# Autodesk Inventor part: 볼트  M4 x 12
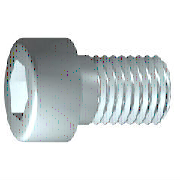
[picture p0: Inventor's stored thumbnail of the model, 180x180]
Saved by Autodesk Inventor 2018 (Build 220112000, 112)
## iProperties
IsCustomPart: 1
Created: 2012-02
Part Number: 볼트  M4 x 12
Material: 강철, 연강
Description: 6각 소켓 머리 캡 나사
Document SubType Name: Modeling
Standard: ISO 4762
Designer: mdu-01
Standard Revision: Fourth edition 2004-03-01
Standards Organization: ISO
Language: ko-KR
Size Designation: M4 x 12
Categories: <MemberInstance><Categories><Category DisplayName="조임쇠" InternalName="e4da775c-781d-43d5-af7c-5136215cf5a6" Mnemonic="FSTN"><Category DisplayName="볼트" InternalN
Density: 7.75 g/cm^3
Appearance: 강철
Author: mdu-01
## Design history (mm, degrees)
sketch "스케치1"
  geometry: L1 (-1, 0)-(12, 0); L2 (12, 0)-(12, 2); L3 (12, 2)-(1.75, 2); L4 (1.75, 2)-(1.32, 2); L5 (1.32, 2)-(0, 2); L6 (0, 2)-(0, 3.5); L7 (0, 3.5)-(-4, 3.5); L8 (-4, 3.5)-(-4, 1.732); L9 (-4, 1.732)-(-2, 1.732); L10 (-2, 1.732)-(-1, 0); L11 (-7.2, 0)-(15.2, 0) reference; L12 (0, -0.7)-(0, 4.2) reference; L13 (1.75, 2)-(0, 2)
  constraints: 22 end point, 6 parallel, 2 collinear, 2 perpendicular, 1 horizontal, 1 point on line
  dimensions: "d1" = 10.25 distance from line of L3.end L2 (= GEL); "d2" = 0.42952 distance of L4.end L3.end (computed from GAL); "d3" = 4 distance between parallel lines of L8 L6 (= KOH); "d4" = 2 distance of L8.end L9.end (= INTI); "d5" = 60 deg angle of L10 L1; "d6" = 4 diameter of L3 L1 (= GD); "d7" = 4 diameter of L5 L1 (= BDM); "d8" = 3.4641 diameter of L9 L1 (= 1.1547 x SW); "d9" = 7 diameter of L7 L1 (= KOD); "d26" = 12 distance between parallel lines of L12 L2 (= NLG)
revolve "본체" sketch "스케치1" stored, may be unused: angle "d10" = 90 deg
sketch "스케치2"
  geometry: L1 (0, -4.9)-(0, 4.9) reference; L2 (-4.9, 0)-(4.9, 0) reference; L3 (1.732, 0)-(0.866, -1.5); L4 (0.866, -1.5)-(-0.866, -1.5); L5 (-0.866, -1.5)-(-1.732, 0); L6 (-1.732, 0)-(-0.866, 1.5); L7 (-0.866, 1.5)-(0.866, 1.5); L8 (0.866, 1.5)-(1.732, 0); 2 further points
  constraints: 12 end point, 1 coincident, 1 horizontal alignment, 1 point on line, 12 other
extrude "슬롯" join sketch "스케치2" stored distance "d11" = 10; taper "d12" = 0 deg
workplane "Work Plane1"
fillet "Fillet2" dims "d30" = 0.1 (= R)
body "Solid1"
fillet "모깎기1" dims "d17" = 0.4 (= RR)
feature "스레드" dims "d13" = 10.25 (= GEL), "d14" = 0
chamfer "모따기1" distance "d15" = 0.42941 (= -0.5 x SPD + 0.5 x GD); stored, may be unused: second distance "d16" = 0.42941 (= GUL), angle "d27" = 45 deg
other parameters: "GD" = 4 [user parameter; used in 2 equation terms], "NLG" = 12 [user parameter; used in 1 equation term], "GEL" = 10.25 [user parameter; used in 2 equation terms], "KOD" = 7 [user parameter; used in 1 equation term], "KOH" = 4 [user parameter; used in 1 equation term], "INTI" = 2 [user parameter; used in 1 equation term], "GAL" = 0.42941 (= 0.61345 x PTC) [user parameter; used in 1 equation term], "GUL" = 0.42941 (= 0.61345 x PTC) [user parameter; used in 1 equation term], "BDM" = 4 (= NND) [user parameter; used in 1 equation term], "SW" = 3 [user parameter; used in 2 equation terms], "RR" = 0.4 [user parameter; used in 1 equation term], "SPD" = 3.14117 (= NND - 1.2269 x PTC) [user parameter; used in 1 equation term], "d19" = 0, "d28" = 0, "d29" = 0, "R" = 0.1 [user parameter; used in 1 equation term], "TOA" = 30 deg [user parameter], "GD1" = 3.14117 (= THREADDIA - 1.2269 x PTC) [user parameter], "THREADDIA" = 4 [user parameter; used in 1 equation term], "FAWI" = 45 deg [user parameter], "TPU" = 14.28571 (computed from PTC) [user parameter], "PTC" = 0.7 [user parameter; used in 5 equation terms], "NND" = 4 [user parameter; used in 2 equation terms], "E0" = 3.465 (= 1.155 x SW) [user parameter]
